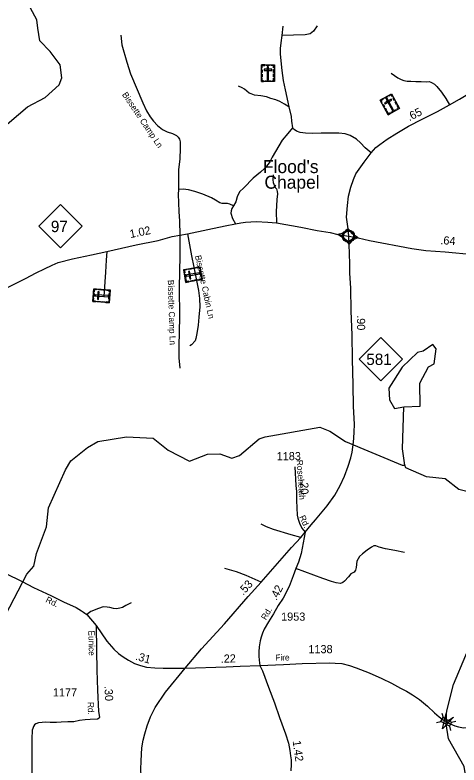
# Model space of a CAD drawing. Extents: x 2220236 to 2384410, y 720751 to 894131.
# Drawn here: x 2261433 to 2268254, y 763290 to 774823 of the extents above; entities that cross this region are included whole.
import ezdxf

# ---------------------------------------------------------------- set-up
doc = ezdxf.new("R2010")
doc.units = 0
for name, color, linetype in [('Exist Civil Demographics Community CELL', 7, 'Continuous'), ('Exist Civil Demographics Community Label', 7, 'Continuous'), ('Exist Cultural Cemetery CELL', 7, 'Continuous'), ('Exist Hydrographic Creek Single Shore', 7, 'Continuous'), ('Exist Hydrographic Misc Water Feature', 7, 'Continuous'), ('Exist Hydrographic Pond Under 1500 Sq Ft', 7, 'Continuous'), ('Exist Road Non-System Type 51', 7, 'Continuous'), ('Exist Road Non-System Type 51 Label', 7, 'Continuous'), ('Exist Road Primary NC Attributed', 7, 'Continuous'), ('Exist Road Primary NC Service Mileage Hundredths English Label', 7, 'Continuous'), ('Exist Road Primary NC Shield CELL', 7, 'Continuous'), ('Exist Road Primary NC Shield Number Label', 7, 'Continuous'), ('Exist Road Secondary Mileage Hundredths English Label', 7, 'Continuous'), ('Exist Road Secondary Structure Standard Bridge Attributed CELL', 7, 'Continuous'), ('Exist Road Secondary Structure Standard Bridge CELL', 7, 'Continuous'), ('Exist Road Secondary Type 51 Attributed', 7, 'Continuous'), ('Exist Road Secondary Type 51 Label', 7, 'Continuous'), ('Exist Road Secondary Type 51 Number Label', 7, 'Continuous')]:
    doc.layers.add(name, color=color, linetype=linetype)

msp = doc.modelspace()

# ---------------------------------------------------------------- linework, layer by layer
at = {"layer": 'Exist Civil Demographics Community CELL'}
msp.add_lwpolyline([(2266478, 771436), (2266479, 771441), (2266481, 771448), (2266484, 771455), (2266486, 771461), (2266490, 771467), (2266494, 771472), (2266498, 771476), (2266502, 771481), (2266508, 771485), (2266513, 771489), (2266518, 771492), (2266523, 771494), (2266528, 771497), (2266534, 771498), (2266538, 771499), (2266543, 771500), (2266547, 771501), (2266554, 771501), (2266558, 771501), (2266564, 771501), (2266569, 771500), (2266574, 771499), (2266579, 771498), (2266584, 771496), (2266591, 771493), (2266597, 771489), (2266602, 771486), (2266607, 771482), (2266610, 771479), (2266614, 771474), (2266618, 771470), (2266621, 771465), (2266625, 771460), (2266627, 771455), (2266629, 771450), (2266631, 771445), (2266632, 771440), (2266633, 771434), (2266634, 771429), (2266634, 771423), (2266634, 771418), (2266633, 771412), (2266632, 771407), (2266630, 771400), (2266629, 771395), (2266626, 771389), (2266623, 771383), (2266620, 771378), (2266616, 771373), (2266612, 771369), (2266607, 771364), (2266602, 771360), (2266597, 771356), (2266593, 771354), (2266586, 771350), (2266579, 771348), (2266573, 771346), (2266566, 771345), (2266562, 771344), (2266557, 771344), (2266552, 771344), (2266547, 771345), (2266542, 771345), (2266536, 771347), (2266531, 771348), (2266526, 771350), (2266521, 771352), (2266517, 771354), (2266511, 771358), (2266505, 771362), (2266500, 771367), (2266496, 771372), (2266493, 771376), (2266490, 771380), (2266485, 771387), (2266484, 771391), (2266482, 771395), (2266479, 771403), (2266478, 771410), (2266477, 771415), (2266477, 771421), (2266477, 771426), (2266477, 771432)], close=True, dxfattribs=at)
for centre, radius in [((2266555, 771423), 94.3), ((2266555, 771424), 76.7)]:
    msp.add_circle(centre, radius, dxfattribs=at)
at = {"layer": 'Exist Cultural Cemetery CELL'}
for points in [[(2265218, 774057), (2265417, 774057), (2265417, 773802), (2265218, 773802)], [(2265218, 774013), (2265230, 774013), (2265230, 774045), (2265270, 774045), (2265270, 774057), (2265218, 774057)], [(2265292, 774057), (2265344, 774057), (2265344, 774045), (2265292, 774045)], [(2265327, 774027), (2265309, 774027), (2265309, 773824), (2265327, 773824)], [(2265418, 774013), (2265406, 774013), (2265406, 774045), (2265366, 774045), (2265366, 774056), (2265418, 774056)], [(2265218, 773939), (2265218, 773982), (2265230, 773982), (2265230, 773939)], [(2265218, 773872), (2265218, 773915), (2265230, 773915), (2265230, 773872)], [(2265259, 773988), (2265259, 773970), (2265377, 773970), (2265377, 773988)], [(2265406, 773940), (2265406, 773983), (2265418, 773983), (2265418, 773940)], [(2265406, 773874), (2265406, 773917), (2265417, 773917), (2265417, 773874)], [(2265251, 773802), (2265251, 773813), (2265229, 773813), (2265229, 773854), (2265218, 773854), (2265218, 773802)], [(2265276, 773813), (2265361, 773813), (2265361, 773802), (2265276, 773802)], [(2265384, 773802), (2265384, 773813), (2265406, 773813), (2265406, 773854), (2265417, 773854), (2265417, 773802)], [(2267042, 773513), (2267216, 773609), (2267339, 773386), (2267165, 773290)], [(2267107, 773549), (2267152, 773574), (2267158, 773564), (2267112, 773539)], [(2267152, 773540), (2267135, 773531), (2267233, 773353), (2267250, 773362)], [(2267237, 773571), (2267228, 773566), (2267212, 773594), (2267176, 773574), (2267171, 773584), (2267217, 773609)], [(2267263, 773502), (2267242, 773540), (2267252, 773545), (2267273, 773507)], [(2267063, 773475), (2267073, 773480), (2267057, 773509), (2267093, 773528), (2267088, 773538), (2267042, 773513)], [(2267099, 773410), (2267078, 773448), (2267088, 773453), (2267109, 773416)], [(2267111, 773473), (2267120, 773457), (2267223, 773514), (2267214, 773530)], [(2267295, 773444), (2267274, 773482), (2267284, 773487), (2267305, 773449)], [(2267310, 773370), (2267305, 773380), (2267324, 773391), (2267305, 773426), (2267314, 773432), (2267339, 773386)], [(2267131, 773351), (2267110, 773389), (2267120, 773395), (2267141, 773357)], [(2267194, 773306), (2267188, 773316), (2267169, 773305), (2267150, 773341), (2267140, 773335), (2267165, 773290)], [(2267210, 773328), (2267284, 773369), (2267290, 773359), (2267215, 773318)], [(2264058, 770712), (2264024, 770908), (2264274, 770952), (2264309, 770756)], [(2264066, 770916), (2264068, 770905), (2264037, 770899), (2264044, 770859), (2264033, 770857), (2264024, 770908)], [(2264140, 770917), (2264098, 770910), (2264096, 770921), (2264138, 770928)], [(2264205, 770929), (2264163, 770921), (2264161, 770932), (2264203, 770940)], [(2264280, 770920), (2264269, 770918), (2264265, 770939), (2264225, 770932), (2264223, 770943), (2264274, 770952)], [(2264288, 770811), (2264273, 770894), (2264284, 770896), (2264299, 770813)], [(2264045, 770785), (2264036, 770836), (2264048, 770838), (2264057, 770787)], [(2264068, 770825), (2264071, 770806), (2264271, 770841), (2264268, 770860)], [(2264118, 770764), (2264136, 770767), (2264116, 770883), (2264098, 770880)], [(2264303, 770789), (2264292, 770787), (2264296, 770765), (2264256, 770758), (2264258, 770747), (2264309, 770756)], [(2264101, 770720), (2264099, 770731), (2264067, 770725), (2264060, 770765), (2264049, 770763), (2264058, 770712)], [(2264174, 770732), (2264131, 770725), (2264129, 770736), (2264172, 770744)], [(2264240, 770744), (2264197, 770737), (2264195, 770748), (2264238, 770755)], [(2262628, 770415), (2262642, 770614), (2262896, 770596), (2262882, 770397)], [(2262633, 770489), (2262637, 770541), (2262648, 770540), (2262645, 770488)], [(2262685, 770611), (2262684, 770599), (2262652, 770601), (2262649, 770561), (2262638, 770562), (2262642, 770614)], [(2262699, 770451), (2262717, 770450), (2262726, 770567), (2262707, 770568)], [(2262757, 770594), (2262714, 770597), (2262715, 770608), (2262758, 770605)], [(2262823, 770590), (2262780, 770593), (2262781, 770604), (2262824, 770601)], [(2262894, 770563), (2262882, 770564), (2262884, 770586), (2262843, 770588), (2262844, 770599), (2262896, 770596)], [(2262671, 770412), (2262672, 770423), (2262640, 770425), (2262643, 770466), (2262632, 770467), (2262628, 770415)], [(2262665, 770522), (2262664, 770503), (2262866, 770489), (2262867, 770508)], [(2262884, 770430), (2262873, 770431), (2262871, 770409), (2262831, 770412), (2262830, 770401), (2262882, 770397)], [(2262875, 770455), (2262881, 770540), (2262892, 770539), (2262886, 770455)], [(2262745, 770407), (2262702, 770410), (2262703, 770421), (2262746, 770418)], [(2262812, 770402), (2262769, 770405), (2262770, 770416), (2262813, 770413)]]:
    msp.add_lwpolyline(points, close=True, dxfattribs=at)
at = {"layer": 'Exist Hydrographic Creek Single Shore'}
for points in [[(2260886, 764833), (2261615, 766222), (2261722, 766348), (2261762, 766540), (2261917, 766950), (2261947, 767242), (2262208, 767827), (2262290, 767969), (2262547, 768171), (2262704, 768266), (2263145, 768335), (2263553, 768314), (2263788, 768132), (2264115, 767961), (2264388, 768070), (2264580, 768073), (2264764, 768010), (2264880, 768050), (2265186, 768303), (2265277, 768337), (2266117, 768487), (2266268, 768422), (2266511, 768266), (2267380, 767901), (2267422, 767900)], [(2269321, 767028), (2268517, 767461), (2268250, 767525), (2268040, 767690), (2267757, 767719), (2267439, 767860), (2267422, 767900)], [(2267252, 759353), (2267385, 759429), (2267773, 759775), (2268076, 760375), (2268437, 760922), (2268567, 761274), (2268613, 761630), (2268594, 761939), (2268405, 762553), (2268393, 762894), (2268332, 763269), (2268094, 763691), (2268058, 763921), (2268058, 763953), (2268061, 764085), (2268074, 764141), (2268170, 764526), (2268357, 764978), (2268537, 765394), (2268816, 765831), (2269080, 766108), (2269185, 766394), (2269321, 767028)]]:
    msp.add_lwpolyline(points, dxfattribs=at)
at = {"layer": 'Exist Hydrographic Misc Water Feature'}
for points in [[(2261784, 774622), (2261767, 774750), (2261538, 775181), (2261545, 775305), (2261711, 775391), (2261777, 775475), (2261791, 775733), (2261865, 775784), (2261898, 775885), (2261904, 776118), (2262028, 776211), (2262036, 776269)], [(2261309, 771391), (2261090, 771599), (2260947, 771788), (2260786, 772071), (2260785, 772212), (2260996, 772778), (2261169, 773024), (2261623, 773411), (2261897, 773553), (2262111, 773749), (2262152, 773856), (2262125, 774057), (2261973, 774263), (2261813, 774427), (2261784, 774620)], [(2261784, 774620), (2261784, 774622)], [(2267422, 767900), (2267386, 768150), (2267405, 768799)]]:
    msp.add_lwpolyline(points, dxfattribs=at)
at = {"layer": 'Exist Hydrographic Pond Under 1500 Sq Ft'}
msp.add_lwpolyline([(2267405, 768799), (2267655, 768810), (2267652, 769161), (2267783, 769411), (2267874, 769461), (2267905, 769687), (2267854, 769754), (2267705, 769652), (2267614, 769634), (2267383, 769409), (2267178, 769082), (2267188, 768905), (2267264, 768772), (2267405, 768799)], dxfattribs=at)
at = {"layer": 'Exist Road Non-System Type 51'}
msp.add_line((2265549, 774652), (2265530, 774506), dxfattribs=at)
for points in [[(2266076, 774657), (2266021, 774576), (2265966, 774532), (2265888, 774519), (2265712, 774514), (2265530, 774506)], [(2263061, 774512), (2263075, 774365), (2263151, 774096), (2263207, 773918), (2263395, 773470), (2263452, 773347), (2263507, 773255), (2263560, 773188), (2263620, 773124), (2263699, 773063), (2263771, 773028), (2263853, 773003), (2263881, 772983), (2263915, 772969), (2263942, 772946), (2263962, 772914), (2263970, 772872), (2263969, 772774), (2263965, 772608), (2263946, 772446), (2263946, 772308), (2263947, 772142)], [(2265530, 774506), (2265515, 774396), (2265506, 774310), (2265507, 774222), (2265531, 773968), (2265555, 773816), (2265584, 773671), (2265642, 773409)], [(2267211, 773928), (2267313, 773859), (2267366, 773833), (2267408, 773818), (2267458, 773808), (2267516, 773803), (2267592, 773801), (2267672, 773802), (2267758, 773797), (2267796, 773799), (2267820, 773792), (2267844, 773780), (2267875, 773758), (2267914, 773723), (2267985, 773637), (2268053, 773538), (2268107, 773443)], [(2265642, 773409), (2265574, 773451), (2265500, 773492), (2265439, 773521), (2265363, 773541), (2265295, 773564), (2265211, 773579), (2265111, 773592), (2265061, 773610), (2265029, 773623), (2264958, 773681), (2264922, 773704), (2264868, 773728)], [(2265642, 773409), (2265676, 773260), (2265683, 773190), (2265697, 773090)], [(2265697, 773090), (2265624, 772999), (2265535, 772899), (2265382, 772635), (2265346, 772567), (2265321, 772527), (2265264, 772464), (2265202, 772406), (2265093, 772315), (2264950, 772164), (2264883, 772103), (2264846, 772029), (2264823, 771948), (2264789, 771890)], [(2266902, 772702), (2266814, 772781), (2266743, 772856), (2266677, 772915), (2266582, 772969), (2266506, 772996), (2266406, 773007), (2266288, 773006), (2266134, 773008), (2266000, 772999), (2265896, 773006), (2265812, 773015), (2265756, 773035), (2265724, 773062), (2265697, 773090)], [(2265398, 772366), (2265393, 772288), (2265397, 772246), (2265428, 772170), (2265450, 772148), (2265462, 772111), (2265465, 772071), (2265453, 771984), (2265448, 771886), (2265445, 771803), (2265448, 771625)], [(2263947, 772142), (2263938, 772062), (2263945, 771940), (2263948, 771794), (2263958, 771656), (2263967, 771439)], [(2264789, 771890), (2264731, 771916), (2264695, 771923), (2264659, 771925), (2264613, 771924), (2264581, 771936), (2264514, 771973), (2264454, 772011), (2264316, 772069), (2264197, 772108), (2264097, 772134), (2264015, 772143), (2263947, 772142)], [(2264789, 771890), (2264762, 771848), (2264752, 771812), (2264748, 771774), (2264772, 771693), (2264821, 771610)], [(2266550, 771537), (2266514, 771510), (2266492, 771486), (2266458, 771462), (2266392, 771447)], [(2266705, 771396), (2266650, 771432), (2266616, 771460), (2266550, 771537)], [(2263967, 771439), (2263965, 771117), (2263957, 770634), (2263962, 770182), (2263948, 769723), (2263952, 769550), (2263965, 769394)], [(2264084, 771459), (2264143, 771118), (2264182, 770947), (2264250, 770584), (2264267, 770464), (2264270, 770336), (2264259, 770178), (2264247, 770052), (2264228, 769926), (2264213, 769850), (2264201, 769812), (2264144, 769751), (2264120, 769733)], [(2266568, 771299), (2266525, 771353), (2266491, 771386), (2266451, 771414), (2266392, 771447)], [(2266705, 771396), (2266633, 771370), (2266568, 771299)], [(2262845, 771185), (2262832, 771054), (2262824, 770870), (2262797, 770492)], [(2265823, 766786), (2265678, 766831), (2265402, 766910), (2265295, 766951), (2265213, 766993)], [(2267419, 766558), (2267267, 766589), (2267124, 766616), (2267026, 766638), (2266975, 766658), (2266945, 766658), (2266909, 766641), (2266843, 766592), (2266772, 766538), (2266723, 766494), (2266682, 766423), (2266675, 766328), (2266665, 766284), (2266645, 766257), (2266594, 766228), (2266555, 766184), (2266497, 766116), (2266470, 766094), (2266431, 766079), (2266367, 766089), (2266297, 766111), (2266162, 766160), (2265749, 766312)], [(2265213, 766100), (2264982, 766202), (2264836, 766259), (2264654, 766310)], [(2263215, 765786), (2263138, 765740), (2263082, 765713), (2263044, 765701), (2262994, 765692), (2262944, 765696), (2262888, 765711), (2262850, 765717), (2262788, 765720), (2262716, 765698), (2262599, 765649), (2262534, 765603)], [(2262586, 763990), (2262510, 763985), (2262425, 763976), (2262339, 763954), (2262246, 763955), (2262141, 763947), (2262071, 763944), (2261975, 763941), (2261907, 763949), (2261793, 763937), (2261754, 763921), (2261733, 763909), (2261716, 763880), (2261703, 763836)]]:
    msp.add_lwpolyline(points, dxfattribs=at)
at = {"layer": 'Exist Road Primary NC Attributed'}
for points in [[(2266561, 771421), (2266550, 771537), (2266528, 771715), (2266541, 771893), (2266558, 772037), (2266594, 772174), (2266631, 772291), (2266670, 772381), (2266796, 772561), (2266902, 772702), (2266977, 772784), (2267038, 772833), (2267150, 772914), (2267297, 773006), (2267480, 773111), (2267689, 773219), (2267924, 773338), (2268107, 773443), (2268263, 773531), (2268392, 773607), (2268511, 773690), (2268638, 773795)], [(2261329, 770638), (2261594, 770771), (2261760, 770856), (2261887, 770921), (2262005, 770974), (2262096, 771016), (2262316, 771071), (2262606, 771134), (2262845, 771185), (2263296, 771288), (2263633, 771356), (2263848, 771415), (2263967, 771439), (2264084, 771459), (2264396, 771522), (2264662, 771581), (2264821, 771610), (2264904, 771625), (2264975, 771637), (2265057, 771644), (2265140, 771647), (2265318, 771639), (2265448, 771625), (2265826, 771561), (2266077, 771510), (2266274, 771478), (2266392, 771447), (2266561, 771421)], [(2265889, 766869), (2265983, 766982), (2266050, 767060), (2266231, 767275), (2266345, 767441), (2266428, 767588), (2266494, 767732), (2266553, 767885), (2266592, 768012), (2266614, 768100), (2266623, 768178), (2266633, 768256), (2266637, 768320), (2266641, 768408), (2266646, 768531), (2266635, 768805), (2266626, 769135), (2266618, 769533), (2266615, 769902), (2266597, 770273), (2266594, 770624), (2266577, 770851), (2266577, 771002), (2266573, 771147), (2266568, 771299), (2266561, 771421)], [(2266561, 771421), (2266705, 771396), (2266877, 771356), (2267531, 771234), (2267746, 771203), (2268041, 771183), (2268477, 771139), (2268904, 771102), (2269124, 771088), (2269392, 771088), (2269621, 771093), (2269802, 771090), (2269921, 771089)], [(2264047, 764780), (2264299, 765077), (2264652, 765462), (2265016, 765883), (2265213, 766100), (2265682, 766633), (2265823, 766786), (2265889, 766869)], [(2263445, 760898), (2263522, 761239), (2263533, 761350), (2263536, 761470), (2263529, 761583), (2263513, 761713), (2263495, 761919), (2263432, 762526), (2263401, 762814), (2263378, 763023), (2263367, 763218), (2263369, 763354), (2263380, 763553), (2263403, 763670), (2263429, 763771), (2263465, 763890), (2263513, 764028), (2263587, 764173), (2263746, 764409), (2264047, 764780)]]:
    msp.add_lwpolyline(points, dxfattribs=at)
at = {"layer": 'Exist Road Primary NC Shield CELL'}
for points in [[(2261797, 771574), (2262130, 771907), (2262463, 771574), (2262130, 771241)], [(2266720, 769531), (2267053, 769864), (2267386, 769531), (2267053, 769198)]]:
    msp.add_lwpolyline(points, close=True, dxfattribs=at)
at = {"layer": 'Exist Road Secondary Structure Standard Bridge Attributed CELL'}
msp.add_lwpolyline([(2268168, 764023), (2267999, 763846), (2268057, 764083), (2268058, 763953)], close=True, dxfattribs=at)
at = {"layer": 'Exist Road Secondary Structure Standard Bridge CELL'}
for p, q in [((2267990, 764089), (2268009, 764022)), ((2267908, 763942), (2267974, 763961)), ((2268106, 763887), (2268125, 763821)), ((2268140, 763948), (2268207, 763966))]:
    msp.add_line(p, q, dxfattribs=at)
msp.add_lwpolyline([(2268009, 764022), (2268141, 763948), (2268106, 763886), (2267974, 763961)], close=True, dxfattribs=at)
at = {"layer": 'Exist Road Secondary Type 51 Attributed'}
for points in [[(2265730, 767875), (2265749, 767590), (2265759, 767497), (2265755, 767359), (2265769, 767134), (2265779, 767084), (2265803, 767009), (2265838, 766932), (2265889, 766869)], [(2265889, 766869), (2265831, 766543), (2265788, 766410), (2265749, 766312), (2265706, 766200), (2265643, 766035), (2265550, 765857), (2265475, 765740), (2265406, 765615), (2265326, 765493), (2265262, 765376), (2265237, 765316), (2265215, 765253), (2265200, 765201), (2265183, 765109), (2265177, 765031), (2265178, 764965), (2265182, 764903), (2265195, 764821)], [(2261281, 766238), (2261542, 766109), (2261718, 766021), (2261984, 765896), (2262179, 765801), (2262372, 765711), (2262457, 765659), (2262484, 765641), (2262504, 765624), (2262534, 765603), (2262679, 765436)], [(2262679, 765436), (2262684, 765052), (2262691, 764747), (2262702, 764441), (2262717, 764110), (2262730, 764023), (2262724, 764009), (2262698, 763994), (2262586, 763990)], [(2262679, 765436), (2262843, 765196), (2262952, 765070), (2263021, 765006), (2263095, 764951), (2263174, 764904), (2263271, 764851), (2263361, 764821), (2263455, 764795), (2263583, 764782), (2263709, 764777), (2263865, 764777), (2264047, 764780)], [(2264047, 764780), (2264676, 764801), (2264892, 764808), (2265195, 764821)], [(2265195, 764821), (2265556, 764834), (2265845, 764850), (2266267, 764863), (2266351, 764858), (2266455, 764851), (2266571, 764822), (2266675, 764783), (2266876, 764705), (2267070, 764622), (2267219, 764546), (2267356, 764472), (2267447, 764424), (2267541, 764368), (2267647, 764298), (2267771, 764194), (2267878, 764092), (2267950, 764028), (2268028, 763974), (2268056, 763959)], [(2265195, 764821), (2265234, 764740), (2265327, 764485), (2265421, 764248), (2265496, 764020), (2265587, 763771), (2265634, 763623), (2265655, 763514), (2265666, 763431), (2265675, 763367), (2265673, 763298), (2265670, 763198)], [(2268056, 763959), (2268106, 763930), (2268189, 763893), (2268247, 763875), (2268322, 763862), (2268420, 763864), (2268533, 763867), (2268607, 763872), (2268738, 763880), (2269906, 763961), (2270415, 764000), (2270691, 764012), (2270880, 764025)], [(2261695, 763077), (2261697, 763383), (2261698, 763682), (2261703, 763836)]]:
    msp.add_lwpolyline(points, dxfattribs=at)

# ---------------------------------------------------------------- texts
at = {"layer": 'Exist Civil Demographics Community Label'}
for s, p in [("Flood's", (2265242, 772392)), ('Chapel', (2265265, 772152))]:
    msp.add_text(s, height=200, dxfattribs=at).set_placement(p)
at = {"layer": 'Exist Road Non-System Type 51 Label'}
for s, rotation, p in [('Bissette Camp Ln', 303.9703, (2263073, 773599)), ('Bissette Cabin Ln', 282.2898, (2264197, 771118)), ('Bissette Camp Ln', 271.7621, (2263780, 770749))]:
    msp.add_text(s, height=95, rotation=rotation, dxfattribs=at).set_placement(p)
at = {"layer": 'Exist Road Primary NC Service Mileage Hundredths English Label'}
for s, rotation, p in [('.65', 27.1103, (2267492, 773188)), ('1.02', 11.4767, (2263207, 771392)), ('.64', 356.2149, (2267964, 771300)), ('.90', 270.5268, (2266686, 770206)), ('.53', 47.661, (2264939, 765892))]:
    msp.add_text(s, height=125, rotation=rotation, dxfattribs=at).set_placement(p)
at = {"layer": 'Exist Road Primary NC Shield Number Label'}
for s, p in [('97', (2261984, 771484)), ('581', (2266830, 769441))]:
    msp.add_text(s, height=175, dxfattribs=at).set_placement(p)
at = {"layer": 'Exist Road Secondary Mileage Hundredths English Label'}
for s, rotation, p in [('.20', 270.5639, (2265815, 767683)), ('.42', 62.7995, (2265450, 765810)), ('.31', 344.5682, (2263274, 764909)), ('.22', 1.7238, (2264595, 764861)), ('.30', 272.6392, (2262807, 764503)), ('1.42', 277.8107, (2265698, 763658))]:
    msp.add_text(s, height=125, rotation=rotation, dxfattribs=at).set_placement(p)
at = {"layer": 'Exist Road Secondary Type 51 Label'}
for s, rotation, p in [('Roseheath', 273.8809, (2265758, 767979)), ('Rd.', 294.767, (2265797, 767104)), ('Rd.', 334.3938, (2261894, 765799)), ('Rd.', 59.6004, (2265288, 765511)), ('Eunice', 270.8686, (2262561, 765357)), ('Fire', 1.1522, (2265433, 764893)), ('Rd.', 270.8686, (2262550, 764258))]:
    msp.add_text(s, height=95, rotation=rotation, dxfattribs=at).set_placement(p)
at = {"layer": 'Exist Road Secondary Type 51 Number Label'}
for s, p in [('1183', (2265453, 767977)), ('1953', (2265521, 765509)), ('1138', (2265940, 765009)), ('1177', (2262015, 764344))]:
    msp.add_text(s, height=125, dxfattribs=at).set_placement(p)

doc.saveas('drawing.dxf')
